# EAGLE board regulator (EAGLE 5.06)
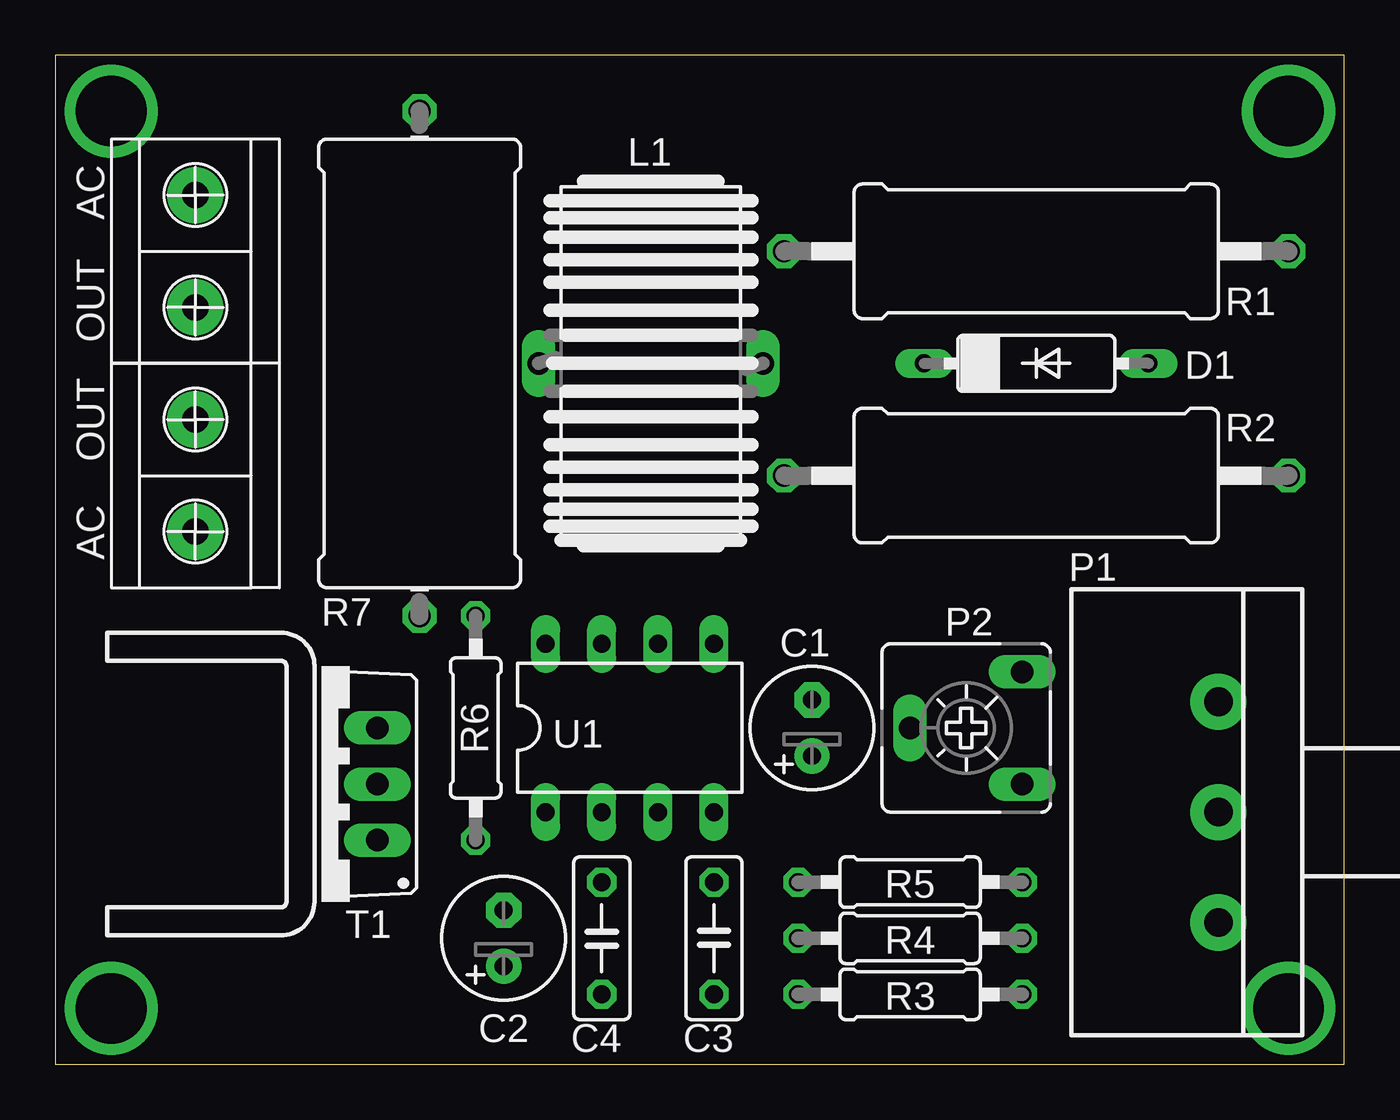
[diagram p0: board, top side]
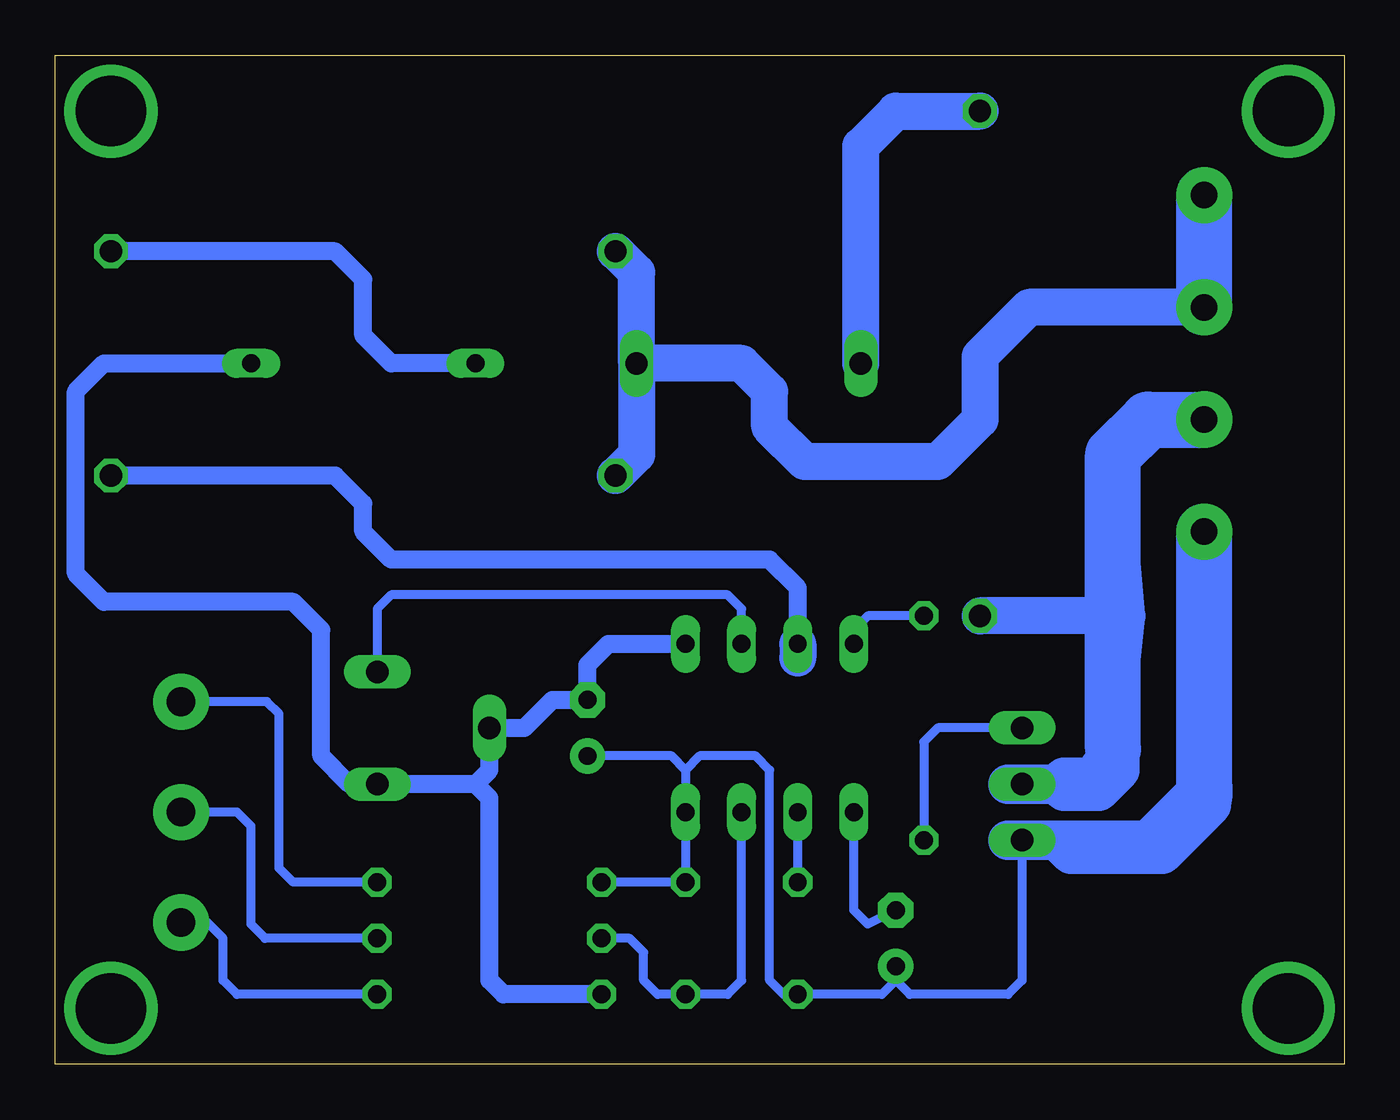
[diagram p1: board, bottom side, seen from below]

Size 58.41 x 45.71 mm. Coordinates in mm from the lower left corner, seen from the top.
Outline: 0,0 58.41,0 58.41,45.71 0,45.71 0,0
Copper layers (1*16): Top 0.035mm / dielectric 1.5mm / Bottom 0.035mm
Design rules "default": minimum track width 10mil, minimum drill 24mil, track to track 8mil, track to pad 8mil, pad to pad 8mil, via to via 8mil, smd to smd 8mil, copper to edge 40mil, drill to drill 8mil, minimum pad ring 10mil, minimum via ring 8mil, stop-mask expansion 4mil, vias tented up to drill 0mil, thermal gap 10mil

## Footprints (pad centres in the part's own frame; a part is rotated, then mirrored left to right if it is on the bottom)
E2,5-6 = drill 0.813 pad 1.6 round: + -1.27,0 | drill 0.813 pad 1.6 octagon: - 1.27,0
C050-025X075 = drill 0.813 octagon: 1 -2.54,0; 2 2.54,0
DO07 = drill 0.813 long: A 5.08,0; C -5.08,0
SFT830S = drill 1.016 long: 1 -5.08,0; 2 5.08,0
CIP20C-4MM = drill 1.3 pad 2.54 round: A -5,0; E 5,0; S 0,0
CA6V = drill 1.016 long: A -2.54,-2.54; E 2.54,-2.54; S 0,2.54
0617/22 = drill 1.016 octagon: 1 -11.43,0; 2 11.43,0
0207/10 = drill 0.813 octagon: 1 -5.08,0; 2 5.08,0
0922/22 = drill 1.016 octagon: 1 -11.43,0; 2 11.43,0
TO220BV = drill 1.016 long: G 2.54,-2.54; T1 -2.54,-2.54; T2 0,-2.54
DIL08 = drill 0.813 long: 1 -3.81,-3.81; 2 -1.27,-3.81; 3 1.27,-3.81; 4 3.81,-3.81; 5 3.81,3.81; 6 1.27,3.81; 7 -1.27,3.81; 8 -3.81,3.81
ARK2 = drill 1.2 pad 2.54 round: 1 -2.54,0; 3 2.54,0 | drill 0.8 pad 2.54 round: 2 2.54,0

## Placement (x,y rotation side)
C1  100uF  [E2,5-6]  34.29,15.24 90 top
C2  4,7uF  [E2,5-6]  20.32,5.71 90 top
C3  100nF  [C050-025X075]  29.85,5.71 90 top
C4  3,3nF  [C050-025X075]  24.76,5.71 270 top
D1  1N4007  [DO07]  44.45,31.75 0 top
L1  100uH/1A  [SFT830S]  26.99,31.75 0 top
P1  47k  [CIP20C-4MM]  52.7,11.43 90 top
P2  1M  [CA6V]  41.28,15.24 90 top
R1  22k/2W  [0617/22]  44.45,36.83 0 top
R2  680k/2W  [0617/22]  44.45,26.67 180 top
R3  15k  [0207/10]  38.73,3.17 180 top
R4  47k  [0207/10]  38.73,5.71 180 top
R5  220k  [0207/10]  38.73,8.26 0 top
R6  180  [0207/10]  19.05,15.24 270 top
R7  33k/5W  [0922/22]  16.51,31.75 270 top
T1  BT138  [TO220BV]  12.06,12.7 90 top
U1  U2008B  [DIL08]  26.04,15.24 0 top
U$1  ARK2  [ARK2]  6.35,36.83 270 top
U$2  ARK2  [ARK2]  6.35,26.67 270 top

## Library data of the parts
C1-C4 R1-R7 = rcl
D1 = diode
L1 = inductors
P1 P2 = pot2
T1 = triac
U1 = ic-package
U$1 U$2 = ark2

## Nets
GND: C1.+ C2.+ C3.2 C4.2 R5.1 T1.T1 U1.4 U$2.2
N$1: P1.A R3.1
N$2: P1.S R4.1
N$3: P1.E R5.2
N$4: C3.1 R4.2 U1.3
N$5: C4.1 U1.2
N$6: C2.- U1.1
N$7: C1.- D1.A P2.A P2.S R3.2 U1.5
N$8: R6.1 U1.8
N$9: R6.2 T1.G
N$11: D1.C R1.2
N$12: P2.E U1.6
N$13: R2.1 U1.7
N$14: L1.1 R7.1
N$15: R7.2 T1.T2 U$2.1
N$16: L1.2 R1.1 R2.2 U$1.1 U$1.2

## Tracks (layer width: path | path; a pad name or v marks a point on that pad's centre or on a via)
GND
  Bottom 0.406: 29.85,13.33 U1.4 C3.2 R5.1 | 29.85,13.33 30.48,13.97 C1.+ | 20.32,3.81 20.96,3.17 C4.2 25.4,3.17 26.04,3.81 26.04,13.33 26.67,13.97 29.21,13.97 29.85,13.33 | 20.32,3.81 C2.+ | T1.T1 14.61,3.81 15.24,3.17 19.68,3.17 20.32,3.81
  Bottom 1.676: 6.35,11.75 6.35,12.06
  Bottom 1.778: 15.24,10.16 T1.T1 13.02,10.16 | 13.02,10.16 8.89,10.16 6.35,12.7 | 6.35,12.06 6.03,11.75 8.25,9.53 12.38,9.53 13.02,10.16
  Bottom 2.54: U$2.2 6.35,12.7 6.35,12.06
N$1
  Bottom 0.406: R3.1 50.17,3.17 50.8,3.81 50.8,5.71 51.52,6.43 P1.A
N$2
  Bottom 0.406: P1.S 50.17,11.43 49.53,10.79 49.53,6.35 48.89,5.71 R4.1
N$3
  Bottom 0.406: R5.2 47.62,8.26 48.26,8.89 48.26,15.87 48.81,16.43 P1.E
N$4
  Bottom 0.406: U1.3 27.3,3.81 27.94,3.17 C3.1 31.11,3.17 31.75,3.81 31.75,5.08 32.39,5.71 R4.2
N$5
  Bottom 0.406: C4.1 U1.2
N$6
  Bottom 0.406: U1.1 22.22,6.98 21.59,6.35 C2.-
N$7
  Bottom 0.813: D1.A 56.2,31.75 57.47,30.48 57.47,22.23 56.2,20.95 47.62,20.95 46.36,19.69 46.36,13.97 45.09,12.7 P2.A 39.37,12.7 | 39.37,12.7 38.73,13.33 P2.S 37.15,15.24 35.88,16.51 C1.- 34.29,18.1 33.34,19.05 U1.5 | R3.2 38.1,3.17 38.73,3.81 38.73,12.06 39.37,12.7
N$8
  Bottom 0.406: R6.1 21.59,20.32 22.22,19.69 U1.8
N$9
  Bottom 0.406: T1.G 18.42,15.24 19.05,14.6 R6.2
N$10  (via drill 3.2)
  other vias: 2.54,2.54
N$11
  Bottom 0.813: D1.C 43.18,31.75 44.45,33.02 44.45,35.56 45.72,36.83 R1.2
N$12
  Bottom 0.406: U1.6 27.3,20.64 27.94,21.27 43.18,21.27 43.81,20.64 P2.E
N$13
  Bottom 0.813: U1.7 24.76,21.59 26.04,22.86 43.18,22.86 44.45,24.13 44.45,25.4 45.72,26.67 R2.1
  Bottom 1.676: U1.7 24.76,18.41
N$14
  Bottom 1.676: L1.1 21.91,41.59 20.32,43.18 R7.1
N$15
  Bottom 1.676: 10.48,14.29 9.84,20.32 | 9.84,20.32 10.48,27.62 | 9.84,20.32 R7.2
  Bottom 1.778: 10.16,15.24 10.16,13.33 11.11,12.38 12.7,12.38 13.02,12.7 | 13.02,12.7 12.06,12.7 11.43,13.02 | 13.02,12.7 T1.T2 15.24,12.7 | 13.02,12.7 12.7,13.02 11.43,13.02 | 11.43,13.02 10.48,14.29
  Bottom 2.54: 10.48,14.29 10.48,27.62 8.89,29.21 U$2.1
N$16
  Bottom 1.676: L1.2 32.07,27.62 R2.2 | L1.2 32.07,35.88 R1.1 | U$1.2 14.29,34.29 16.51,32.07 16.51,29.21 18.42,27.3 24.45,27.3 26.04,28.89 26.04,30.48 27.3,31.75 L1.2
  Bottom 2.54: U$1.2 U$1.1
N$17  (via drill 3.2)
  other vias: 55.88,43.18 2.54,43.18
N$18  (via drill 3.2)
  other vias: 55.88,2.54

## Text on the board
tPlace: AC | OUT | OUT | AC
